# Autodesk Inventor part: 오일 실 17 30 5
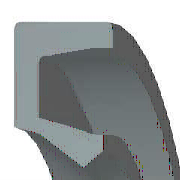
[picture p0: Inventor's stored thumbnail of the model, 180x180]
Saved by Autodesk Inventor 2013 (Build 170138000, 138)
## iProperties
IsCustomPart: 1
Created: 2012-02
Part Number: 오일 실 17 30 5
Material: 고무
Description: 오일 실 - 비스프링, 금속 케이스 GM
Document SubType Name: Modeling
Standard: JIS B 2402
Designer: mduedu
Standards Organization: JIS
Language: ko-KR
Size Designation: 17 30 5 B
Categories: <MemberInstance><Categories><Category DisplayName="샤프트 부품" InternalName="7f7aeb1f-a693-4053-b835-cee3144e0d98" Mnemonic="SHFT"><Category DisplayName="실링" Intern
Density: 0.93 g/cm^3
Mass: 0.924459 g
Surface Area: 18.6212 cm^2
Volume: 0.994042 cm^3
Author: mduedu
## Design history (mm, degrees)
body "Solid1"
revolve "회전1" stored, may be unused: angle "d27" = 360 deg
fillet "모깎기1" dims "d28" = 0.25 (= 0.05 x b)
chamfer "모따기1" distance "d29" = 0.07143 (= 0.0142857 x b); stored, may be unused: second distance "d30" = 0.25 (= 0.05 x b), angle "d35" = 45 deg
sketch "스케치2"
  geometry: L1 (-9.367, -3.238)-(-10.233, -3.863); L2 (-8.5, -1.625)-(-9.367, -3.238); L3 (-9.15, -1)-(-8.5, -1.625); L4 (-11.317, -3.75)-(-9.15, -1); L5 (-13.075, -3.75)-(-11.317, -3.75); L6 (-14.375, -1.25)-(-13.075, -3.75); L7 (-14.375, 0)-(-14.375, -1.25); L8 (-15, 0)-(-14.375, 0); L9 (-15, -5)-(-15, 0); L10 (-11.129, -5)-(-15, -5); L11 (-10.233, -3.863)-(-11.129, -5); L12 (0, -9.6)-(0, 1.6) reference; L13 (-14, 0)-(-28, 0) reference
  constraints: 22 end point, 3 horizontal, 2 vertical, 1 parallel
  dimensions: "d2" = 5 distance of L9.start L8.start (= b); "d4" = 1 vertical distance of L8.start L3.start (= 0.2 x b); "d6" = 0.625 distance of L8.start L7.start (= 0.125 x b); "d8" = 1.25 distance of L7.start L6.start (= 0.25 x b); "d10" = 1.25 vertical distance of L5.start L9.start (= 0.25 x b); "d12" = 1.3 horizontal distance of L6.start L5.start (= 0.1 x dd - 0.1 x Diam); "d14" = 1.6129 vertical distance of L2.start L1.start (= 0.322581 x b); "d16" = 0.86667 horizontal distance of L1.start L1.end (= 0.0666667 x dd - 0.0666667 x Diam); "d18" = 0.86667 horizontal distance of L2.start L1.start (= 0.0666667 x dd - 0.0666667 x Diam); "d20" = 0.625 vertical distance of L3.start L2.start (= 0.125 x b); "d22" = 0.65 horizontal distance of L3.start L2.start (= 0.05 x dd - 0.05 x Diam); "d24" = 0.625 vertical distance of L1.start L1.end (= 0.125 x b); "d26" = 2.16667 horizontal distance of L4.start L3.start (= 0.166667 x dd - 0.166667 x Diam); "d31" = 0 distance between parallel lines of L8 L13; "d32" = 15 distance between parallel lines of L12 L9 (= 0.5 x dd); "d33" = 8.5 distance from line of L12 L2.start (= 0.5 x Diam)
other parameters: "Diam" = 17 [user parameter; used in 6 equation terms], "b" = 5 [user parameter; used in 11 equation terms], "d1" = 8 (derived), "d3" = 1.6 (derived), "d5" = 1 (derived), "d7" = 2 (derived), "d9" = 2 (derived), "d11" = 2 (derived), "d13" = 2.58065 (derived), "d15" = 1.33333 (derived), "d17" = 1.33333 (derived), "d19" = 1 (derived), "d21" = 1 (derived), "d23" = 1 (derived), "d25" = 3.33333 (derived), "d34" = 0
